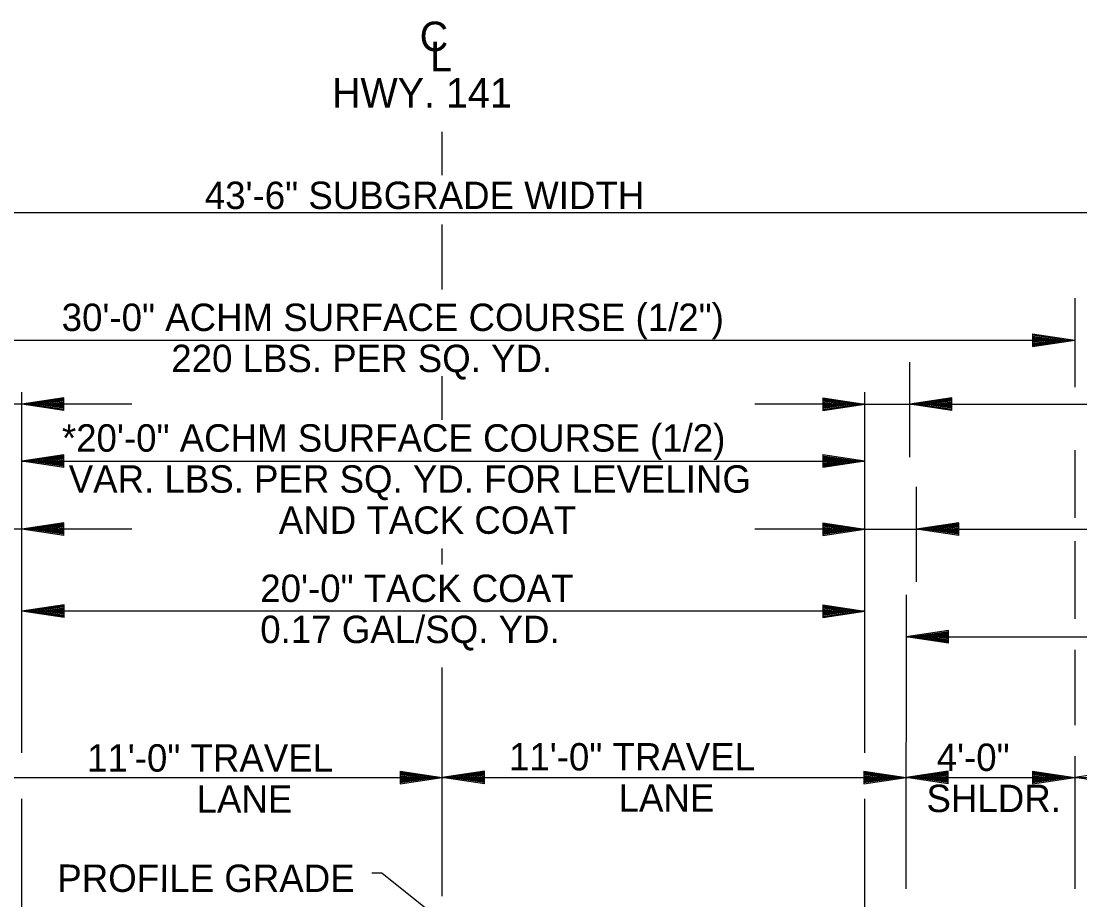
# Model space of a CAD drawing. Extents: x 6848689 to 6848907, y 1900908 to 1901005.
# Drawn here: x 6848736.11 to 6848761.22, y 1900929.32 to 1900950.17 of the extents above; entities that cross this region are included whole.
import ezdxf

# ---------------------------------------------------------------- set-up
doc = ezdxf.new("R2010")
doc.units = 0
for name, color, linetype in [('Default', 7, 'Continuous'), ('R_Draft', 7, 'Continuous'), ('R_No Plot', 7, 'Continuous')]:
    doc.layers.add(name, color=color, linetype=linetype)

msp = doc.modelspace()

# ---------------------------------------------------------------- linework, layer by layer
at = {"layer": 'Default'}
msp.add_line((6848735.099, 1900932.224), (6848757.099, 1900932.224), dxfattribs=at)
at = {"layer": 'R_Draft'}
for p, q in [((6848760.1, 1900942.746), (6848761.1, 1900942.596)), ((6848760.1, 1900942.746), (6848760.1, 1900942.446)), ((6848760.1, 1900942.721), (6848760.933, 1900942.596)), ((6848760.1, 1900942.695), (6848760.761, 1900942.596)), ((6848760.1, 1900942.67), (6848760.594, 1900942.596)), ((6848760.1, 1900942.644), (6848760.425, 1900942.596)), ((6848760.1, 1900942.619), (6848760.258, 1900942.596)), ((6848760.1, 1900942.446), (6848761.1, 1900942.596)), ((6848760.1, 1900942.547), (6848760.425, 1900942.596)), ((6848760.1, 1900942.496), (6848760.761, 1900942.596)), ((6848760.1, 1900942.471), (6848760.933, 1900942.596)), ((6848760.1, 1900942.521), (6848760.594, 1900942.596)), ((6848760.1, 1900942.572), (6848760.258, 1900942.596)), ((6848737.124, 1900941.232), (6848736.124, 1900941.082)), ((6848737.124, 1900940.932), (6848737.124, 1900941.232)), ((6848755.124, 1900941.232), (6848756.124, 1900941.082)), ((6848755.124, 1900941.232), (6848755.124, 1900940.932)), ((6848758.189, 1900941.232), (6848757.189, 1900941.082)), ((6848758.189, 1900940.932), (6848758.189, 1900941.232)), ((6848737.124, 1900940.932), (6848736.124, 1900941.082)), ((6848737.124, 1900941.207), (6848736.291, 1900941.082)), ((6848737.124, 1900940.957), (6848736.291, 1900941.082)), ((6848737.124, 1900941.182), (6848736.463, 1900941.082)), ((6848737.124, 1900940.983), (6848736.463, 1900941.082)), ((6848737.124, 1900941.157), (6848736.63, 1900941.082)), ((6848737.124, 1900941.008), (6848736.63, 1900941.082)), ((6848737.124, 1900941.131), (6848736.799, 1900941.082)), ((6848737.124, 1900941.034), (6848736.799, 1900941.082)), ((6848737.124, 1900941.106), (6848736.966, 1900941.082)), ((6848737.124, 1900941.059), (6848736.966, 1900941.082)), ((6848755.124, 1900941.207), (6848755.957, 1900941.082)), ((6848755.124, 1900941.182), (6848755.785, 1900941.082)), ((6848755.124, 1900941.157), (6848755.619, 1900941.082)), ((6848755.124, 1900941.131), (6848755.449, 1900941.082)), ((6848755.124, 1900941.106), (6848755.282, 1900941.082)), ((6848755.124, 1900940.932), (6848756.124, 1900941.082)), ((6848755.124, 1900941.033), (6848755.449, 1900941.082)), ((6848755.124, 1900940.983), (6848755.785, 1900941.082)), ((6848755.124, 1900940.957), (6848755.957, 1900941.082)), ((6848755.124, 1900941.008), (6848755.619, 1900941.082)), ((6848755.124, 1900941.059), (6848755.282, 1900941.082)), ((6848758.189, 1900940.932), (6848757.189, 1900941.082)), ((6848758.189, 1900941.207), (6848757.356, 1900941.082)), ((6848758.189, 1900940.957), (6848757.356, 1900941.082)), ((6848758.189, 1900941.182), (6848757.528, 1900941.082)), ((6848758.189, 1900940.983), (6848757.528, 1900941.082)), ((6848758.189, 1900941.157), (6848757.694, 1900941.082)), ((6848758.189, 1900941.008), (6848757.694, 1900941.082)), ((6848758.189, 1900941.131), (6848757.864, 1900941.082)), ((6848758.189, 1900941.034), (6848757.864, 1900941.082)), ((6848758.189, 1900941.106), (6848758.031, 1900941.082)), ((6848758.189, 1900941.059), (6848758.031, 1900941.082)), ((6848737.125, 1900939.88), (6848736.125, 1900939.73)), ((6848737.125, 1900939.58), (6848736.125, 1900939.73)), ((6848737.125, 1900939.855), (6848736.292, 1900939.73)), ((6848737.125, 1900939.605), (6848736.292, 1900939.73)), ((6848737.125, 1900939.83), (6848736.464, 1900939.73)), ((6848737.125, 1900939.631), (6848736.464, 1900939.73)), ((6848737.125, 1900939.805), (6848736.631, 1900939.73)), ((6848737.125, 1900939.656), (6848736.631, 1900939.73)), ((6848737.125, 1900939.779), (6848736.8, 1900939.73)), ((6848737.125, 1900939.682), (6848736.8, 1900939.73)), ((6848737.125, 1900939.754), (6848736.967, 1900939.73)), ((6848737.125, 1900939.707), (6848736.967, 1900939.73)), ((6848737.125, 1900939.58), (6848737.125, 1900939.88)), ((6848755.124, 1900939.882), (6848756.124, 1900939.732)), ((6848755.124, 1900939.882), (6848755.124, 1900939.582)), ((6848755.124, 1900939.857), (6848755.957, 1900939.732)), ((6848755.124, 1900939.831), (6848755.785, 1900939.732)), ((6848755.124, 1900939.806), (6848755.619, 1900939.732)), ((6848755.124, 1900939.78), (6848755.449, 1900939.732)), ((6848755.124, 1900939.755), (6848755.282, 1900939.732)), ((6848755.124, 1900939.582), (6848756.124, 1900939.732)), ((6848755.124, 1900939.683), (6848755.449, 1900939.732)), ((6848755.124, 1900939.632), (6848755.785, 1900939.732)), ((6848755.124, 1900939.607), (6848755.957, 1900939.732)), ((6848755.124, 1900939.657), (6848755.619, 1900939.732)), ((6848755.124, 1900939.708), (6848755.282, 1900939.732)), ((6848737.124, 1900938.267), (6848736.124, 1900938.117)), ((6848737.124, 1900938.242), (6848736.291, 1900938.117)), ((6848737.124, 1900938.216), (6848736.463, 1900938.117)), ((6848737.124, 1900937.967), (6848737.124, 1900938.267)), ((6848755.124, 1900938.267), (6848756.124, 1900938.117)), ((6848755.124, 1900938.267), (6848755.124, 1900937.967)), ((6848755.124, 1900938.242), (6848755.957, 1900938.117)), ((6848755.124, 1900938.216), (6848755.785, 1900938.117)), ((6848758.35, 1900938.267), (6848757.35, 1900938.117)), ((6848758.35, 1900938.242), (6848757.517, 1900938.117)), ((6848758.35, 1900938.216), (6848757.689, 1900938.117)), ((6848758.35, 1900937.967), (6848758.35, 1900938.267)), ((6848737.124, 1900937.967), (6848736.124, 1900938.117)), ((6848737.124, 1900937.992), (6848736.291, 1900938.117)), ((6848737.124, 1900938.017), (6848736.463, 1900938.117)), ((6848737.124, 1900938.191), (6848736.63, 1900938.117)), ((6848737.124, 1900938.042), (6848736.63, 1900938.117)), ((6848737.124, 1900938.166), (6848736.799, 1900938.117)), ((6848737.124, 1900938.068), (6848736.799, 1900938.117)), ((6848737.124, 1900938.14), (6848736.966, 1900938.117)), ((6848737.124, 1900938.093), (6848736.966, 1900938.117)), ((6848755.124, 1900938.191), (6848755.619, 1900938.117)), ((6848755.124, 1900938.165), (6848755.449, 1900938.117)), ((6848755.124, 1900938.14), (6848755.282, 1900938.117)), ((6848755.124, 1900937.967), (6848756.124, 1900938.117)), ((6848755.124, 1900938.068), (6848755.449, 1900938.117)), ((6848755.124, 1900938.017), (6848755.785, 1900938.117)), ((6848755.124, 1900937.992), (6848755.957, 1900938.117)), ((6848755.124, 1900938.042), (6848755.619, 1900938.117)), ((6848755.124, 1900938.093), (6848755.282, 1900938.117)), ((6848758.35, 1900937.967), (6848757.35, 1900938.117)), ((6848758.35, 1900937.992), (6848757.517, 1900938.117)), ((6848758.35, 1900938.017), (6848757.689, 1900938.117)), ((6848758.35, 1900938.191), (6848757.856, 1900938.117)), ((6848758.35, 1900938.042), (6848757.856, 1900938.117)), ((6848758.35, 1900938.166), (6848758.025, 1900938.117)), ((6848758.35, 1900938.068), (6848758.025, 1900938.117)), ((6848758.35, 1900938.14), (6848758.192, 1900938.117)), ((6848758.35, 1900938.093), (6848758.192, 1900938.117)), ((6848737.128, 1900936.318), (6848736.128, 1900936.168)), ((6848737.128, 1900936.293), (6848736.295, 1900936.168)), ((6848737.128, 1900936.267), (6848736.467, 1900936.168)), ((6848737.128, 1900936.242), (6848736.633, 1900936.168)), ((6848737.128, 1900936.217), (6848736.803, 1900936.168)), ((6848737.128, 1900936.018), (6848737.128, 1900936.318)), ((6848755.124, 1900936.32), (6848756.124, 1900936.17)), ((6848755.124, 1900936.32), (6848755.124, 1900936.02)), ((6848755.124, 1900936.295), (6848755.957, 1900936.17)), ((6848755.124, 1900936.269), (6848755.785, 1900936.17)), ((6848755.124, 1900936.244), (6848755.619, 1900936.17)), ((6848755.124, 1900936.218), (6848755.449, 1900936.17)), ((6848737.128, 1900936.018), (6848736.128, 1900936.168)), ((6848737.128, 1900936.043), (6848736.295, 1900936.168)), ((6848737.128, 1900936.068), (6848736.467, 1900936.168)), ((6848737.128, 1900936.093), (6848736.633, 1900936.168)), ((6848737.128, 1900936.119), (6848736.803, 1900936.168)), ((6848737.128, 1900936.191), (6848736.97, 1900936.168)), ((6848737.128, 1900936.144), (6848736.97, 1900936.168)), ((6848755.124, 1900936.193), (6848755.282, 1900936.17)), ((6848755.124, 1900936.02), (6848756.124, 1900936.17)), ((6848755.124, 1900936.121), (6848755.449, 1900936.17)), ((6848755.124, 1900936.07), (6848755.785, 1900936.17)), ((6848755.124, 1900936.045), (6848755.957, 1900936.17)), ((6848755.124, 1900936.095), (6848755.619, 1900936.17)), ((6848755.124, 1900936.146), (6848755.282, 1900936.17)), ((6848758.103, 1900935.706), (6848757.103, 1900935.556)), ((6848758.103, 1900935.406), (6848758.103, 1900935.706)), ((6848758.103, 1900935.406), (6848757.103, 1900935.556)), ((6848758.103, 1900935.681), (6848757.27, 1900935.556)), ((6848758.103, 1900935.431), (6848757.27, 1900935.556)), ((6848758.103, 1900935.656), (6848757.442, 1900935.556)), ((6848758.103, 1900935.457), (6848757.442, 1900935.556)), ((6848758.103, 1900935.631), (6848757.609, 1900935.556)), ((6848758.103, 1900935.482), (6848757.609, 1900935.556)), ((6848758.103, 1900935.605), (6848757.778, 1900935.556)), ((6848758.103, 1900935.508), (6848757.778, 1900935.556)), ((6848758.103, 1900935.58), (6848757.945, 1900935.556)), ((6848758.103, 1900935.533), (6848757.945, 1900935.556)), ((6848745.099, 1900932.374), (6848746.099, 1900932.224)), ((6848745.099, 1900932.374), (6848745.099, 1900932.074)), ((6848745.099, 1900932.349), (6848745.932, 1900932.224)), ((6848745.099, 1900932.323), (6848745.76, 1900932.224)), ((6848745.099, 1900932.298), (6848745.594, 1900932.224)), ((6848745.099, 1900932.272), (6848745.424, 1900932.224)), ((6848745.099, 1900932.247), (6848745.257, 1900932.224)), ((6848745.099, 1900932.074), (6848746.099, 1900932.224)), ((6848745.099, 1900932.175), (6848745.424, 1900932.224)), ((6848745.099, 1900932.124), (6848745.76, 1900932.224)), ((6848745.099, 1900932.099), (6848745.932, 1900932.224)), ((6848745.099, 1900932.149), (6848745.594, 1900932.224)), ((6848745.099, 1900932.2), (6848745.257, 1900932.224)), ((6848747.099, 1900932.374), (6848746.099, 1900932.224)), ((6848747.099, 1900932.074), (6848746.099, 1900932.224)), ((6848747.099, 1900932.349), (6848746.266, 1900932.224)), ((6848747.099, 1900932.099), (6848746.266, 1900932.224)), ((6848747.099, 1900932.323), (6848746.438, 1900932.224)), ((6848747.099, 1900932.124), (6848746.438, 1900932.224)), ((6848747.099, 1900932.298), (6848746.605, 1900932.224)), ((6848747.099, 1900932.149), (6848746.605, 1900932.224)), ((6848747.099, 1900932.273), (6848746.774, 1900932.224)), ((6848747.099, 1900932.175), (6848746.774, 1900932.224)), ((6848747.099, 1900932.247), (6848746.941, 1900932.224)), ((6848747.099, 1900932.2), (6848746.941, 1900932.224)), ((6848747.099, 1900932.074), (6848747.099, 1900932.374)), ((6848756.1, 1900932.374), (6848757.1, 1900932.224)), ((6848756.1, 1900932.374), (6848756.1, 1900932.074)), ((6848756.1, 1900932.349), (6848756.933, 1900932.224)), ((6848756.1, 1900932.323), (6848756.761, 1900932.224)), ((6848756.1, 1900932.298), (6848756.594, 1900932.224)), ((6848756.1, 1900932.272), (6848756.425, 1900932.224)), ((6848756.1, 1900932.247), (6848756.258, 1900932.224)), ((6848756.1, 1900932.074), (6848757.1, 1900932.224)), ((6848756.1, 1900932.175), (6848756.425, 1900932.224)), ((6848756.1, 1900932.124), (6848756.761, 1900932.224)), ((6848756.1, 1900932.099), (6848756.933, 1900932.224)), ((6848756.1, 1900932.149), (6848756.594, 1900932.224)), ((6848756.1, 1900932.2), (6848756.258, 1900932.224)), ((6848758.1, 1900932.374), (6848757.1, 1900932.224)), ((6848758.1, 1900932.074), (6848757.1, 1900932.224)), ((6848758.1, 1900932.349), (6848757.267, 1900932.224)), ((6848758.1, 1900932.099), (6848757.267, 1900932.224)), ((6848758.1, 1900932.323), (6848757.439, 1900932.224)), ((6848758.1, 1900932.124), (6848757.439, 1900932.224)), ((6848758.1, 1900932.298), (6848757.605, 1900932.224)), ((6848758.1, 1900932.149), (6848757.605, 1900932.224)), ((6848758.1, 1900932.273), (6848757.775, 1900932.224)), ((6848758.1, 1900932.175), (6848757.775, 1900932.224)), ((6848758.1, 1900932.247), (6848757.942, 1900932.224)), ((6848758.1, 1900932.2), (6848757.942, 1900932.224)), ((6848758.1, 1900932.074), (6848758.1, 1900932.374)), ((6848760.1, 1900932.374), (6848761.1, 1900932.224)), ((6848760.1, 1900932.374), (6848760.1, 1900932.074)), ((6848760.1, 1900932.349), (6848760.933, 1900932.224)), ((6848760.1, 1900932.323), (6848760.761, 1900932.224)), ((6848760.1, 1900932.298), (6848760.594, 1900932.224)), ((6848760.1, 1900932.272), (6848760.425, 1900932.224)), ((6848760.1, 1900932.247), (6848760.258, 1900932.224)), ((6848760.1, 1900932.074), (6848761.1, 1900932.224)), ((6848760.1, 1900932.175), (6848760.425, 1900932.224)), ((6848760.1, 1900932.124), (6848760.761, 1900932.224)), ((6848760.1, 1900932.099), (6848760.933, 1900932.224)), ((6848760.1, 1900932.149), (6848760.594, 1900932.224)), ((6848760.1, 1900932.2), (6848760.258, 1900932.224)), ((6848762.1, 1900932.374), (6848761.1, 1900932.224)), ((6848762.1, 1900932.074), (6848761.1, 1900932.224))]:
    msp.add_line(p, q, dxfattribs=at)
msp.add_lwpolyline([(6848746.097, 1900928.807), (6848744.67, 1900929.952), (6848744.426, 1900929.955)], dxfattribs=at)
at = {"layer": 'R_No Plot'}
for p, q in [((6848746.097, 1900946.516), (6848746.097, 1900947.545)), ((6848724.258, 1900945.628), (6848767.936, 1900945.628)), ((6848746.097, 1900943.8), (6848746.097, 1900945.343)), ((6848761.1, 1900943.596), (6848761.1, 1900941.484)), ((6848731.099, 1900942.596), (6848761.1, 1900942.596)), ((6848757.189, 1900939.826), (6848757.189, 1900942.08)), ((6848746.097, 1900941.413), (6848746.097, 1900941.745)), ((6848736.124, 1900932.81), (6848736.124, 1900941.367)), ((6848746.097, 1900940.71), (6848746.097, 1900941.413)), ((6848756.124, 1900932.81), (6848756.124, 1900941.367)), ((6848736.124, 1900941.082), (6848712.301, 1900941.082)), ((6848738.734, 1900941.082), (6848736.124, 1900941.082)), ((6848756.124, 1900941.082), (6848753.514, 1900941.082)), ((6848756.124, 1900941.082), (6848780.413, 1900941.082)), ((6848761.1, 1900939.99), (6848761.1, 1900938.379)), ((6848736.125, 1900939.73), (6848756.124, 1900939.73)), ((6848757.35, 1900936.863), (6848757.35, 1900939.117)), ((6848736.124, 1900938.117), (6848712.301, 1900938.117)), ((6848738.734, 1900938.117), (6848736.124, 1900938.117)), ((6848756.124, 1900938.117), (6848753.514, 1900938.117)), ((6848756.124, 1900938.117), (6848780.413, 1900938.117)), ((6848761.1, 1900937.828), (6848761.1, 1900935.987)), ((6848746.097, 1900937.273), (6848746.097, 1900937.657)), ((6848757.104, 1900936.556), (6848757.097, 1900929.576)), ((6848756.124, 1900936.17), (6848736.124, 1900936.17)), ((6848757.103, 1900935.556), (6848771.103, 1900935.556)), ((6848761.1, 1900935.251), (6848761.1, 1900933.462)), ((6848746.097, 1900929.403), (6848746.097, 1900934.832)), ((6848761.1, 1900932.724), (6848761.1, 1900929.576)), ((6848757.1, 1900932.224), (6848761.1, 1900932.224)), ((6848761.1, 1900932.224), (6848767.936, 1900932.224)), ((6848736.124, 1900928.282), (6848736.124, 1900931.716)), ((6848756.124, 1900928.281), (6848756.124, 1900931.716))]:
    msp.add_line(p, q, dxfattribs=at)

# ---------------------------------------------------------------- texts
at = {"layer": 'R_Draft'}
for s, height, p in [('C', 0.7, (6848745.564, 1900949.457)), ('L', 0.7, (6848745.81, 1900948.98)), ('HWY. 141', 0.7, (6848743.483, 1900948.116)), ('43\'-6" SUBGRADE WIDTH', 0.65, (6848740.467, 1900945.71)), ('30\'-0" ACHM SURFACE COURSE (1/2")', 0.65, (6848737.072, 1900942.816)), ('220 LBS. PER SQ. YD.', 0.65, (6848739.672, 1900941.841)), ('*20\'-0" ACHM SURFACE COURSE (1/2)', 0.65, (6848737.078, 1900939.953)), ('VAR. LBS. PER SQ. YD. FOR LEVELING', 0.65, (6848737.239, 1900938.978)), ('AND TACK COAT', 0.65, (6848742.224, 1900938.003)), ('20\'-0" TACK COAT', 0.65, (6848741.783, 1900936.386)), ('0.17 GAL/SQ. YD.', 0.65, (6848741.783, 1900935.411)), ('11\'-0" TRAVEL ', 0.65, (6848737.673, 1900932.36)), ('11\'-0" TRAVEL ', 0.65, (6848747.682, 1900932.388)), (' 4\'-0"', 0.65, (6848757.585, 1900932.376)), ('LANE', 0.65, (6848740.273, 1900931.385)), ('LANE', 0.65, (6848750.282, 1900931.413)), ('SHLDR.', 0.65, (6848757.585, 1900931.401))]:
    msp.add_text(s, height=height, dxfattribs=at).set_placement(p)
msp.add_text('PROFILE GRADE', height=0.65, rotation=359.98, dxfattribs=at).set_placement((6848736.969, 1900929.507))

doc.saveas('drawing.dxf')
